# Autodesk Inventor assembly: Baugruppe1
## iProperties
Shininess: 64.0
Length Units: 11269
Angle Units: 11279
Time Units: 11290
Mass Units: 11283
Length Display Precision: 3
Angle Display Precision: 2
Compacted: True
Created: 2003-11
Part Number: Baugruppe1
Document SubType Name: Assembly
Designer: HJ
Manufacturer: Standard
Standards Organization: Custom
Density: 0.0
Volumn: 0.0
Area: 0.0
PropertySet Name: Model Information
Control State: 0
Master: False
Checked Out: False
Author: HJ
